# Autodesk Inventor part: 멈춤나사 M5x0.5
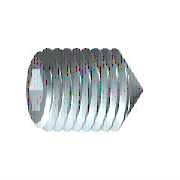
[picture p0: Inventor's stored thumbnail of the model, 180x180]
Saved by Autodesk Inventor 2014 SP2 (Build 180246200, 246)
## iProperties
Company: 한국ATC센터
IsCustomPart: 1
Created: 2014-10
Part Number: 멈춤나사 M5x0.5
Material: 강철, 연강
Description: 6각 소켓 머리 없는 멈춤 나사
Document SubType Name: Modeling
Standard: KS B 1028
Designer: 한국ATC센터
Standards Organization: KS
Language: ko-KR
Size Designation: 원추점 M5x10
Categories: <MemberInstance><Categories><Category DisplayName="조임쇠" InternalName="e4da775c-781d-43d5-af7c-5136215cf5a6" Mnemonic="FSTN"><Category DisplayName="볼트" InternalN
Density: 7.86 g/cm^3
Mass: 1.16912 g
Surface Area: 1.91683 cm^2
Volume: 0.148743 cm^3
Appearance: 강철
Author: KYOUNG IL JANG
Revision Number: 1
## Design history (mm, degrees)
sketch "스케치1"
  geometry: L1 (0, 0)-(6.167, 0); L2 (10, 1.443)-(10, 2.5); L3 (10, 2.5)-(0, 2.5); L4 (10, 1.443)-(7, 1.443); L5 (7, 1.443)-(6.167, 0); L6 (0, -0.5)-(0, 3) reference; L7 (0, 2.5)-(0, 0)
  constraints: 13 end point, 3 parallel, 1 collinear, 1 perpendicular, 1 point on line
  dimensions: "d0" = 3 distance of L2.start L4.end (= INTI); "d1" = 60 deg angle of L5 L1; "d2" = 5 diameter of L3 L1 (= NND); "d3" = 2.88675 diameter of L4 L1 (= 1.1547 x SW); "d5" = 10 distance from line of L2 L3.end (= NLG)
revolve "본체" sketch "스케치1" stored, may be unused: angle "d6" = 90 deg
sketch "스케치2"
  geometry: L1 (-0.722, 1.25)-(0.722, 1.25); L2 (0.722, 1.25)-(1.443, 0); L3 (1.443, 0)-(0.722, -1.25); L4 (0.722, -1.25)-(-0.722, -1.25); L5 (-0.722, -1.25)-(-1.443, 0); L6 (-1.443, 0)-(-0.722, 1.25); 3 further points
  constraints: 12 end point, 1 coincident, 1 horizontal, 13 other
extrude "슬롯" join sketch "스케치2" taper "d7" = 0 deg; stored distance "d21" = 10
workaxis "Work Axis1"
workplane "Work Plane1"
body "Solid1"
feature "스레드" dims "d12" = 10 (= NLG), "d13" = 0
chamfer "모따기1" distance "d8" = 2.25 (computed from NND, SPD, FAWI); stored, may be unused: angle "d9" = 45 deg (= FAWI), second distance "d34" = 2.25 (computed from NND, SPD, FAWI)
chamfer "모따기2" distance "d10" = 0.49076 (= -0.5 x GD1 + 0.5 x NND); stored, may be unused: angle "d11" = 45 deg (= FAWI), second distance "d35" = 0.49076 (= -0.5 x GD1 + 0.5 x NND)
other parameters: "NND" = 5 [user parameter; used in 5 equation terms], "NLG" = 10 [user parameter; used in 2 equation terms], "INTI" = 3 [user parameter; used in 1 equation term], "FAWI" = 45 deg [user parameter; used in 4 equation terms], "SW" = 2.5 [user parameter; used in 2 equation terms], "GD1" = 4.01848 (= THREADDIA - 1.2269 x PTC) [user parameter; used in 2 equation terms], "d4" = 0, "FAWI1" = 45 deg [user parameter], "SPD" = 0.5 [user parameter; used in 2 equation terms], "d36" = 0, "d37" = 0, "GUL" = 0.49076 (= 0.61345 x PTC) [user parameter], "TPU" = 12.5 (computed from PTC) [user parameter], "TOA" = 30 deg [user parameter], "THREADDIA" = 5 [user parameter; used in 1 equation term], "PTC" = 0.8 [user parameter; used in 4 equation terms], "GAL" = 0.49076 (= 0.61345 x PTC) [user parameter], "E0" = 2.8875 (= 1.155 x SW) [user parameter]
